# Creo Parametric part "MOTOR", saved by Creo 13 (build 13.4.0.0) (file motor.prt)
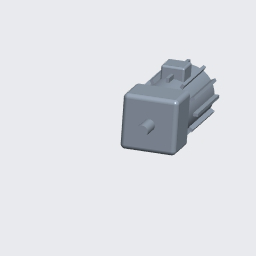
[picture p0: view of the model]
Units: millimeter Newton Second (mmNs); MM, TONNE, SECS

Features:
  1. datum plane "RIGHT"
  2. datum plane "TOP"
  3. datum plane "FRONT"
  4. coordinate system
  5. protrusion
  6. protrusion
  7. protrusion
  8. protrusion
  9. datum axis
  10. pattern
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
Surfaces: 61 plane, 15 cylinder, 6 torus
